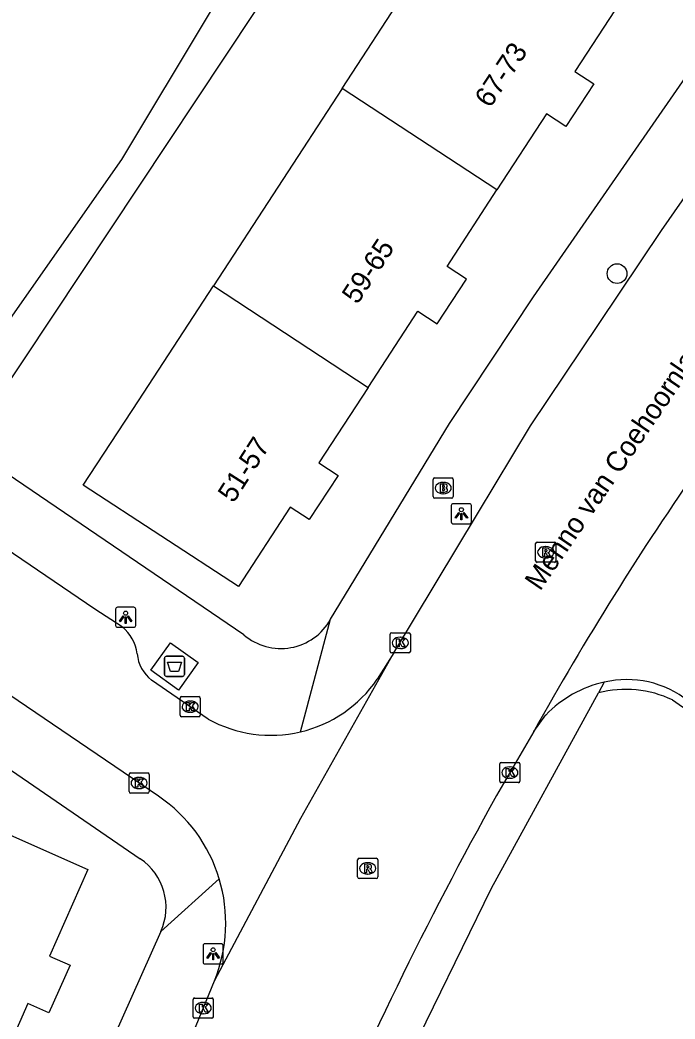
# Model space of a CAD drawing. Extents: x 160026 to 161302, y 384757 to 385701.
# Drawn here: x 160195.38 to 160227.82, y 385434.76 to 385484.27 of the extents above; entities that cross this region are included whole.
import ezdxf

# ---------------------------------------------------------------- set-up
doc = ezdxf.new("R2010")
doc.units = 0
for name, color, linetype in [('IMGEO_Afval_apart_plaats', 7, 'Continuous'), ('IMGEO_Boom', 7, 'Continuous'), ('IMGEO_Brandkraan', 7, 'Continuous'), ('IMGEO_Kolk', 7, 'Continuous'), ('IMGEO_Lichtpunt', 7, 'Continuous'), ('IMGEO_Openbare_ruimte_label', 7, 'Continuous'), ('IMGEO_Pand', 7, 'Continuous'), ('IMGEO_Pand_nummerreeks', 7, 'Continuous'), ('IMGEO_Rijbaan_lokaal_gesloten', 7, 'Continuous'), ('IMGEO_Rijbaan_lokaal_open', 7, 'Continuous'), ('IMGEO_Rioolput', 7, 'Continuous'), ('IMGEO_Voetpad_gesloten', 7, 'Continuous'), ('IMGEO_Voetpad_open', 7, 'Continuous')]:
    doc.layers.add(name, color=color, linetype=linetype)

msp = doc.modelspace()

# ---------------------------------------------------------------- linework, layer by layer
at = {"layer": 'IMGEO_Afval_apart_plaats'}
for p, q in [((160202.534, 385451.837), (160202.534, 385452.637)), ((160202.534, 385452.637), (160202.534, 385451.837)), ((160202.634, 385452.737), (160203.424, 385452.737)), ((160203.424, 385452.737), (160202.634, 385452.737)), ((160203.524, 385452.637), (160203.524, 385451.837)), ((160203.524, 385451.837), (160203.524, 385452.637)), ((160203.424, 385451.737), (160202.634, 385451.737)), ((160202.634, 385451.737), (160203.424, 385451.737))]:
    msp.add_line(p, q, dxfattribs=at)
msp.add_lwpolyline([(160202.677, 385452.451), (160203.381, 385452.451), (160203.232, 385451.981), (160202.826, 385451.981), (160202.677, 385452.451)], dxfattribs=at)
for centre, start, end in [((160202.634, 385452.637), 90, 180), ((160202.634, 385452.637), 90, 180), ((160203.424, 385452.637), 0, 90), ((160203.424, 385452.637), 360, 90), ((160202.634, 385451.837), 180, 270), ((160202.634, 385451.837), 180, 270), ((160203.424, 385451.837), 270, 0), ((160203.424, 385451.837), 270, 0)]:
    msp.add_arc(centre, 0.1, start, end, dxfattribs=at)
at = {"layer": 'IMGEO_Boom'}
msp.add_circle((160224.952, 385471.697), 0.489, dxfattribs=at)
at = {"layer": 'IMGEO_Brandkraan'}
for p, q in [((160215.841, 385460.648), (160215.841, 385461.5)), ((160215.916, 385461.574), (160216.768, 385461.574)), ((160216.842, 385461.5), (160216.842, 385460.648)), ((160216.329, 385461.354), (160216.354, 385461.354)), ((160216.768, 385460.574), (160215.916, 385460.574)), ((160216.352, 385460.794), (160216.327, 385460.794))]:
    msp.add_line(p, q, dxfattribs=at)
for points in [[(160215.841, 385460.648), (160215.841, 385461.5)], [(160215.916, 385461.574), (160216.768, 385461.574)], [(160216.842, 385461.5), (160216.842, 385460.648)], [(160216.189, 385461.274), (160216.189, 385460.874), (160216.402, 385460.874)], [(160216.42, 385461.274), (160216.189, 385461.274)], [(160216.368, 385461.193), (160216.314, 385461.193), (160216.314, 385461.117)], [(160216.314, 385461.117), (160216.367, 385461.117)], [(160216.376, 385461.041), (160216.314, 385461.041), (160216.314, 385460.96)], [(160216.314, 385460.96), (160216.376, 385460.96)], [(160216.768, 385460.574), (160215.916, 385460.574)]]:
    msp.add_lwpolyline(points, dxfattribs=at)
for centre, radius, start, end in [((160215.918, 385461.498), 0.0765, 91.552, 178.448), ((160215.918, 385461.498), 0.0765, 91.552, 178.448), ((160216.766, 385461.498), 0.0765, 1.552, 88.448), ((160216.766, 385461.498), 0.0765, 1.552, 88.448), ((160216.369, 385461.155), 0.0379, 267.8285, 90.9355), ((160216.377, 385461), 0.0404, 269.8759, 90.5077), ((160216.408, 385461.125), 0.251, 268.6676, 293.5347), ((160216.424, 385461.129), 0.145, 59.4692, 91.5367), ((160216.449, 385461.176), 0.0922, 285.5137, 58.1501), ((160216.454, 385460.984), 0.105, 301.3115, 78.989), ((160215.918, 385460.65), 0.0765, 181.552, 268.448), ((160215.918, 385460.65), 0.0765, 181.552, 268.448), ((160216.766, 385460.65), 0.0765, 271.552, 358.448), ((160216.766, 385460.65), 0.0765, 271.552, 358.448)]:
    msp.add_arc(centre, radius, start, end, dxfattribs=at)
for centre, major_axis, ratio, start_param, end_param in [((160216.328, 385461.074), (-0.387, 0.002), 0.722429, 4.712389, 7.853982), ((160216.353, 385461.074), (-0.39, 0.002), 0.717154, 1.570796, 4.712389)]:
    msp.add_ellipse(centre, major_axis=major_axis, ratio=ratio, start_param=start_param, end_param=end_param, dxfattribs=at)
at = {"layer": 'IMGEO_Kolk'}
for p, q in [((160213.714, 385452.975), (160213.714, 385453.827)), ((160213.789, 385453.901), (160214.641, 385453.901)), ((160214.202, 385453.681), (160214.227, 385453.681)), ((160214.715, 385453.827), (160214.715, 385452.975)), ((160214.225, 385453.121), (160214.2, 385453.121)), ((160214.641, 385452.901), (160213.789, 385452.901)), ((160203.307, 385449.815), (160203.307, 385450.667)), ((160203.382, 385450.741), (160204.234, 385450.741)), ((160203.795, 385450.521), (160203.82, 385450.521)), ((160204.308, 385450.667), (160204.308, 385449.815)), ((160204.234, 385449.741), (160203.382, 385449.741)), ((160203.818, 385449.961), (160203.793, 385449.961)), ((160219.142, 385446.549), (160219.142, 385447.401)), ((160219.217, 385447.475), (160220.069, 385447.475)), ((160219.63, 385447.255), (160219.655, 385447.255)), ((160220.143, 385447.401), (160220.143, 385446.549)), ((160200.779, 385446.031), (160200.779, 385446.883)), ((160200.854, 385446.957), (160201.706, 385446.957)), ((160201.267, 385446.737), (160201.292, 385446.737)), ((160201.78, 385446.883), (160201.78, 385446.031)), ((160219.653, 385446.695), (160219.628, 385446.695)), ((160201.29, 385446.177), (160201.265, 385446.177)), ((160220.069, 385446.475), (160219.217, 385446.475)), ((160201.706, 385445.957), (160200.854, 385445.957)), ((160203.954, 385434.878), (160203.954, 385435.73)), ((160204.029, 385435.804), (160204.881, 385435.804)), ((160204.955, 385435.73), (160204.955, 385434.878)), ((160204.442, 385435.584), (160204.467, 385435.584)), ((160204.881, 385434.804), (160204.029, 385434.804)), ((160204.465, 385435.024), (160204.44, 385435.024))]:
    msp.add_line(p, q, dxfattribs=at)
for points in [[(160213.714, 385452.975), (160213.714, 385453.827)], [(160213.789, 385453.901), (160214.641, 385453.901)], [(160214.035, 385453.601), (160214.158, 385453.601), (160214.158, 385453.45), (160214.288, 385453.601), (160214.452, 385453.601), (160214.306, 385453.45), (160214.459, 385453.201), (160214.307, 385453.201), (160214.222, 385453.365), (160214.158, 385453.298), (160214.158, 385453.201), (160214.035, 385453.201), (160214.035, 385453.601)], [(160214.715, 385453.827), (160214.715, 385452.975)], [(160214.641, 385452.901), (160213.789, 385452.901)], [(160203.307, 385449.815), (160203.307, 385450.667)], [(160203.382, 385450.741), (160204.234, 385450.741)], [(160204.308, 385450.667), (160204.308, 385449.815)], [(160203.628, 385450.441), (160203.751, 385450.441), (160203.751, 385450.29), (160203.881, 385450.441), (160204.045, 385450.441), (160203.899, 385450.29), (160204.052, 385450.041), (160203.9, 385450.041), (160203.815, 385450.205), (160203.751, 385450.138), (160203.751, 385450.041), (160203.628, 385450.041), (160203.628, 385450.441)], [(160204.234, 385449.741), (160203.382, 385449.741)], [(160219.142, 385446.549), (160219.142, 385447.401)], [(160219.217, 385447.475), (160220.069, 385447.475)], [(160219.463, 385447.175), (160219.586, 385447.175), (160219.586, 385447.024), (160219.716, 385447.175), (160219.88, 385447.175), (160219.734, 385447.024), (160219.887, 385446.775), (160219.735, 385446.775), (160219.65, 385446.939), (160219.586, 385446.872), (160219.586, 385446.775), (160219.463, 385446.775), (160219.463, 385447.175)], [(160220.143, 385447.401), (160220.143, 385446.549)], [(160200.779, 385446.031), (160200.779, 385446.883)], [(160200.854, 385446.957), (160201.706, 385446.957)], [(160201.1, 385446.657), (160201.223, 385446.657), (160201.223, 385446.506), (160201.353, 385446.657), (160201.517, 385446.657), (160201.371, 385446.506), (160201.524, 385446.257), (160201.372, 385446.257), (160201.287, 385446.421), (160201.223, 385446.354), (160201.223, 385446.257), (160201.1, 385446.257), (160201.1, 385446.657)], [(160201.78, 385446.883), (160201.78, 385446.031)], [(160220.069, 385446.475), (160219.217, 385446.475)], [(160201.706, 385445.957), (160200.854, 385445.957)], [(160203.954, 385434.878), (160203.954, 385435.73)], [(160204.029, 385435.804), (160204.881, 385435.804)], [(160204.955, 385435.73), (160204.955, 385434.878)], [(160204.275, 385435.504), (160204.398, 385435.504), (160204.398, 385435.353), (160204.528, 385435.504), (160204.692, 385435.504), (160204.546, 385435.353), (160204.699, 385435.104), (160204.547, 385435.104), (160204.462, 385435.268), (160204.398, 385435.201), (160204.398, 385435.104), (160204.275, 385435.104), (160204.275, 385435.504)], [(160204.881, 385434.804), (160204.029, 385434.804)]]:
    msp.add_lwpolyline(points, dxfattribs=at)
for centre, start, end in [((160213.791, 385453.825), 91.552, 178.448), ((160213.791, 385453.825), 91.552, 178.448), ((160214.639, 385453.825), 1.552, 88.448), ((160214.639, 385453.825), 1.552, 88.448), ((160213.791, 385452.977), 181.552, 268.448), ((160213.791, 385452.977), 181.552, 268.448), ((160214.639, 385452.977), 271.552, 358.448), ((160214.639, 385452.977), 271.552, 358.448), ((160203.384, 385450.665), 91.552, 178.448), ((160203.384, 385450.665), 91.552, 178.448), ((160204.232, 385450.665), 1.552, 88.448), ((160204.232, 385450.665), 1.552, 88.448), ((160203.384, 385449.817), 181.552, 268.448), ((160203.384, 385449.817), 181.552, 268.448), ((160204.232, 385449.817), 271.552, 358.448), ((160204.232, 385449.817), 271.552, 358.448), ((160219.219, 385447.399), 91.552, 178.448), ((160219.219, 385447.399), 91.552, 178.448), ((160220.067, 385447.399), 1.552, 88.448), ((160220.067, 385447.399), 1.552, 88.448), ((160200.856, 385446.881), 91.552, 178.448), ((160200.856, 385446.881), 91.552, 178.448), ((160201.704, 385446.881), 1.552, 88.448), ((160201.704, 385446.881), 1.552, 88.448), ((160219.219, 385446.551), 181.552, 268.448), ((160219.219, 385446.551), 181.552, 268.448), ((160220.067, 385446.551), 271.552, 358.448), ((160220.067, 385446.551), 271.552, 358.448), ((160200.856, 385446.033), 181.552, 268.448), ((160200.856, 385446.033), 181.552, 268.448), ((160201.704, 385446.033), 271.552, 358.448), ((160201.704, 385446.033), 271.552, 358.448), ((160204.031, 385435.728), 91.552, 178.448), ((160204.031, 385435.728), 91.552, 178.448), ((160204.879, 385435.728), 1.552, 88.448), ((160204.879, 385435.728), 1.552, 88.448), ((160204.031, 385434.88), 181.552, 268.448), ((160204.031, 385434.88), 181.552, 268.448), ((160204.879, 385434.88), 271.552, 358.448), ((160204.879, 385434.88), 271.552, 358.448)]:
    msp.add_arc(centre, 0.0765, start, end, dxfattribs=at)
for centre, major_axis, ratio, start_param, end_param in [((160214.201, 385453.401), (-0.387, 0.002), 0.722429, 4.712389, 7.853982), ((160214.226, 385453.401), (-0.39, 0.002), 0.717154, 1.570796, 4.712389), ((160203.794, 385450.241), (-0.387, 0.002), 0.722429, 4.712389, 7.853982), ((160203.819, 385450.241), (-0.39, 0.002), 0.717154, 1.570796, 4.712389), ((160219.629, 385446.975), (-0.387, 0.002), 0.722429, 4.712389, 7.853982), ((160219.654, 385446.975), (-0.39, 0.002), 0.717154, 1.570796, 4.712389), ((160201.266, 385446.457), (-0.387, 0.002), 0.722429, 4.712389, 7.853982), ((160201.291, 385446.457), (-0.39, 0.002), 0.717154, 1.570796, 4.712389), ((160204.441, 385435.304), (-0.387, 0.002), 0.722429, 4.712389, 7.853982), ((160204.466, 385435.304), (-0.39, 0.002), 0.717154, 1.570796, 4.712389)]:
    msp.add_ellipse(centre, major_axis=major_axis, ratio=ratio, start_param=start_param, end_param=end_param, dxfattribs=at)
at = {"layer": 'IMGEO_Lichtpunt'}
for p, q in [((160216.742, 385460.201), (160216.742, 385459.394)), ((160216.742, 385460.201), (160216.742, 385459.394)), ((160217.644, 385460.296), (160216.836, 385460.296)), ((160217.644, 385460.296), (160216.836, 385460.296)), ((160217.738, 385459.394), (160217.738, 385460.201)), ((160217.738, 385459.394), (160217.738, 385460.201)), ((160216.836, 385459.3), (160217.644, 385459.3)), ((160216.836, 385459.3), (160217.644, 385459.3)), ((160200.113, 385455.075), (160200.113, 385454.268)), ((160200.113, 385455.075), (160200.113, 385454.268)), ((160201.015, 385455.17), (160200.207, 385455.17)), ((160201.015, 385455.17), (160200.207, 385455.17)), ((160201.109, 385454.268), (160201.109, 385455.075)), ((160201.109, 385454.268), (160201.109, 385455.075)), ((160200.207, 385454.174), (160201.015, 385454.174)), ((160200.207, 385454.174), (160201.015, 385454.174)), ((160204.447, 385438.394), (160204.447, 385437.587)), ((160204.447, 385438.394), (160204.447, 385437.587)), ((160205.349, 385438.489), (160204.541, 385438.489)), ((160205.349, 385438.489), (160204.541, 385438.489)), ((160205.443, 385437.587), (160205.443, 385438.394)), ((160205.443, 385437.587), (160205.443, 385438.394)), ((160204.541, 385437.493), (160205.349, 385437.493)), ((160204.541, 385437.493), (160205.349, 385437.493))]:
    msp.add_line(p, q, dxfattribs=at)
for points in [[(160217.116, 385459.865), (160217.155, 385459.837), (160216.967, 385459.575), (160216.929, 385459.602), (160217.116, 385459.865)], [(160217.218, 385459.817), (160217.265, 385459.817), (160217.265, 385459.495), (160217.218, 385459.495), (160217.218, 385459.817)], [(160217.328, 385459.837), (160217.366, 385459.864), (160217.553, 385459.602), (160217.514, 385459.574), (160217.328, 385459.837)], [(160200.487, 385454.739), (160200.526, 385454.711), (160200.338, 385454.449), (160200.3, 385454.476), (160200.487, 385454.739)], [(160200.589, 385454.691), (160200.636, 385454.691), (160200.636, 385454.369), (160200.589, 385454.369), (160200.589, 385454.691)], [(160200.699, 385454.711), (160200.737, 385454.738), (160200.924, 385454.476), (160200.885, 385454.448), (160200.699, 385454.711)], [(160204.821, 385438.058), (160204.86, 385438.03), (160204.672, 385437.768), (160204.634, 385437.795), (160204.821, 385438.058)], [(160204.923, 385438.01), (160204.97, 385438.01), (160204.97, 385437.688), (160204.923, 385437.688), (160204.923, 385438.01)], [(160205.033, 385438.03), (160205.071, 385438.057), (160205.258, 385437.795), (160205.219, 385437.767), (160205.033, 385438.03)]]:
    msp.add_lwpolyline(points, dxfattribs=at)
for centre in [(160217.241, 385459.999), (160200.612, 385454.873), (160204.946, 385438.192)]:
    msp.add_circle(centre, 0.0994, dxfattribs=at)
for centre, start, end in [((160216.836, 385460.201), 90, 180), ((160216.836, 385460.201), 90, 180), ((160217.644, 385460.201), 0, 90), ((160217.644, 385460.201), 0, 90), ((160216.836, 385459.394), 180, 270), ((160216.836, 385459.394), 180, 270), ((160217.644, 385459.394), 270, 0), ((160217.644, 385459.394), 270, 360), ((160200.207, 385455.075), 90, 180), ((160200.207, 385455.075), 90, 180), ((160201.015, 385455.075), 0, 90), ((160201.015, 385455.075), 0, 90), ((160200.207, 385454.268), 180, 270), ((160200.207, 385454.268), 180, 270), ((160201.015, 385454.268), 270, 0), ((160201.015, 385454.268), 270, 360), ((160204.541, 385438.394), 90, 180), ((160204.541, 385438.394), 90, 180), ((160205.349, 385438.394), 0, 90), ((160205.349, 385438.394), 0, 90), ((160204.541, 385437.587), 180, 270), ((160204.541, 385437.587), 180, 270), ((160205.349, 385437.587), 270, 0), ((160205.349, 385437.587), 270, 360)]:
    msp.add_arc(centre, 0.0946, start, end, dxfattribs=at)
at = {"layer": 'IMGEO_Pand'}
for points in [[(160211.338, 385480.879), (160217.716, 385490.66), (160221.229, 385488.37), (160225.417, 385485.639), (160222.862, 385481.721), (160223.802, 385481.107), (160222.422, 385478.99), (160221.46, 385479.617), (160219.002, 385475.848)], [(160211.338, 385480.879), (160204.96, 385471.099)], [(160219.002, 385475.848), (160211.338, 385480.879)], [(160212.629, 385466.064), (160215.087, 385469.833), (160216.041, 385469.211), (160217.489, 385471.432), (160216.53, 385472.058), (160219.002, 385475.848)], [(160212.629, 385466.064), (160210.185, 385462.317), (160211.131, 385461.7), (160209.706, 385459.515), (160208.766, 385460.128), (160206.202, 385456.196), (160198.512, 385461.212), (160201.244, 385465.401), (160204.96, 385471.099)], [(160204.96, 385471.099), (160212.629, 385466.064)], [(160185.543, 385435.246), (160190.285, 385445.923), (160198.736, 385442.169), (160196.832, 385437.882), (160197.864, 385437.424), (160196.815, 385435.064), (160195.773, 385435.527), (160193.983, 385431.497)]]:
    msp.add_lwpolyline(points, dxfattribs=at)
at = {"layer": 'IMGEO_Rijbaan_lokaal_gesloten'}
for points in [[(160213.889, 385452.911), (160218.042, 385459.796), (160220.662, 385464.164), (160224.069, 385469.234), (160227.148, 385473.834), (160229.85, 385477.702), (160233.05, 385482.043), (160237.154, 385487.587), (160240.762, 385492.238), (160247.036, 385500), (160248.366, 385501.543), (160249.437, 385502.831)], [(160205.006, 385436.649), (160209.284, 385444.718), (160213.889, 385452.911)], [(160220.83, 385449.016), (160218.975, 385445.832)], [(160202.176, 385429.732), (160205.006, 385436.649)]]:
    msp.add_lwpolyline(points, dxfattribs=at)
for centre, radius, start, end in [((160357.629, 385372.773), 156.611, 145.14571, 150.86761), ((160401.739, 385344.741), 208.859, 151.05207, 156.9001)]:
    msp.add_arc(centre, radius, start, end, dxfattribs=at)
at = {"layer": 'IMGEO_Rijbaan_lokaal_open'}
for points in [[(160200.435, 385454.194), (160199.088, 385455.07), (160180.167, 385467.938), (160175.915, 385470.845)], [(160202.245, 385445.802), (160185.235, 385457.355)], [(160213.889, 385452.911), (160213.073, 385451.597)], [(160204.698, 385449.628), (160201.897, 385451.558)], [(160220.83, 385449.016), (160221.42, 385449.828)]]:
    msp.add_lwpolyline(points, dxfattribs=at)
for centre, radius, start, end in [((160199.215, 385452.641), 1.975, 6.3384, 51.8582), ((160203.067, 385453.054), 1.899, 185.8816, 231.973), ((160207.805, 385455.206), 6.385, 283.2337, 325.5863), ((160225.436, 385446.716), 4.869, 51.2626, 103.2253), ((160225.581, 385445.811), 5.783, 102.5731, 136.0111), ((160207.806, 385455.207), 6.386, 240.8774, 283.2242), ((160197.984, 385439.524), 7.587, 16.7816, 55.833), ((160197.987, 385439.523), 7.584, 337.7317, 16.7985)]:
    msp.add_arc(centre, radius, start, end, dxfattribs=at)
at = {"layer": 'IMGEO_Rioolput'}
for p, q in [((160220.919, 385457.467), (160220.919, 385458.319)), ((160220.994, 385458.393), (160221.846, 385458.393)), ((160221.407, 385458.173), (160221.432, 385458.173)), ((160221.92, 385458.319), (160221.92, 385457.467)), ((160221.43, 385457.613), (160221.405, 385457.613)), ((160221.846, 385457.393), (160220.994, 385457.393)), ((160212.101, 385441.802), (160212.101, 385442.654)), ((160212.176, 385442.728), (160213.028, 385442.728)), ((160213.102, 385442.654), (160213.102, 385441.802)), ((160212.589, 385442.508), (160212.614, 385442.508)), ((160213.028, 385441.728), (160212.176, 385441.728)), ((160212.612, 385441.948), (160212.587, 385441.948))]:
    msp.add_line(p, q, dxfattribs=at)
for points in [[(160220.919, 385457.467), (160220.919, 385458.319)], [(160220.994, 385458.393), (160221.846, 385458.393)], [(160221.508, 385458.091), (160221.256, 385458.093), (160221.256, 385457.693)], [(160221.434, 385458.012), (160221.38, 385458.012), (160221.38, 385457.931)], [(160221.38, 385457.931), (160221.432, 385457.931)], [(160221.92, 385458.319), (160221.92, 385457.467)], [(160221.256, 385457.693), (160221.38, 385457.693), (160221.38, 385457.855), (160221.391, 385457.855)], [(160221.438, 385457.826), (160221.509, 385457.693), (160221.649, 385457.693), (160221.584, 385457.819)], [(160221.846, 385457.393), (160220.994, 385457.393)], [(160212.101, 385441.802), (160212.101, 385442.654)], [(160212.176, 385442.728), (160213.028, 385442.728)], [(160213.102, 385442.654), (160213.102, 385441.802)], [(160212.69, 385442.426), (160212.438, 385442.428), (160212.438, 385442.028)], [(160212.438, 385442.028), (160212.562, 385442.028), (160212.562, 385442.19), (160212.573, 385442.19)], [(160212.616, 385442.347), (160212.562, 385442.347), (160212.562, 385442.266)], [(160212.562, 385442.266), (160212.614, 385442.266)], [(160212.62, 385442.161), (160212.691, 385442.028), (160212.831, 385442.028), (160212.766, 385442.154)], [(160213.028, 385441.728), (160212.176, 385441.728)]]:
    msp.add_lwpolyline(points, dxfattribs=at)
for centre, radius, start, end in [((160220.996, 385458.317), 0.0765, 91.552, 178.448), ((160220.996, 385458.317), 0.0765, 91.552, 178.448), ((160221.416, 385458.12), 0.19, 274.7715, 282.9687), ((160221.44, 385457.916), 0.0964, 77.0061, 93.1865), ((160221.454, 385457.973), 0.0378, 276.6634, 79.6772), ((160221.507, 385457.981), 0.109, 350.3612, 89.416), ((160221.505, 385457.981), 0.112, 277.5842, 350.9817), ((160221.844, 385458.317), 0.0765, 1.552, 88.448), ((160221.844, 385458.317), 0.0765, 1.552, 88.448), ((160220.996, 385457.469), 0.0765, 181.552, 268.448), ((160220.996, 385457.469), 0.0765, 181.552, 268.448), ((160221.39, 385457.802), 0.0533, 26.0293, 88.6989), ((160221.489, 385457.766), 0.108, 29.5134, 73.7905), ((160221.844, 385457.469), 0.0765, 271.552, 358.448), ((160221.844, 385457.469), 0.0765, 271.552, 358.448), ((160212.178, 385442.652), 0.0765, 91.552, 178.448), ((160212.178, 385442.652), 0.0765, 91.552, 178.448), ((160213.026, 385442.652), 0.0765, 1.552, 88.448), ((160213.026, 385442.652), 0.0765, 1.552, 88.448), ((160212.572, 385442.137), 0.0533, 26.0293, 88.6989), ((160212.598, 385442.455), 0.19, 274.7715, 282.9687), ((160212.622, 385442.251), 0.0964, 77.0061, 93.1865), ((160212.636, 385442.308), 0.0378, 276.6634, 79.6772), ((160212.689, 385442.316), 0.109, 350.3612, 89.416), ((160212.687, 385442.316), 0.112, 277.5842, 350.9817), ((160212.671, 385442.101), 0.108, 29.5134, 73.7905), ((160212.178, 385441.804), 0.0765, 181.552, 268.448), ((160212.178, 385441.804), 0.0765, 181.552, 268.448), ((160213.026, 385441.804), 0.0765, 271.552, 358.448), ((160213.026, 385441.804), 0.0765, 271.552, 358.448)]:
    msp.add_arc(centre, radius, start, end, dxfattribs=at)
for centre, major_axis, ratio, start_param, end_param in [((160221.406, 385457.893), (-0.387, 0.002), 0.722429, 4.712389, 7.853982), ((160221.431, 385457.893), (-0.39, 0.002), 0.717154, 1.570796, 4.712389), ((160212.588, 385442.228), (-0.387, 0.002), 0.722429, 4.712389, 7.853982), ((160212.613, 385442.228), (-0.39, 0.002), 0.717154, 1.570796, 4.712389)]:
    msp.add_ellipse(centre, major_axis=major_axis, ratio=ratio, start_param=start_param, end_param=end_param, dxfattribs=at)
at = {"layer": 'IMGEO_Voetpad_gesloten'}
msp.add_lwpolyline([(160202.826, 385453.408), (160204.203, 385452.427), (160203.233, 385451.065), (160201.856, 385452.046), (160202.826, 385453.408)], dxfattribs=at)
at = {"layer": 'IMGEO_Voetpad_open'}
for points in [[(160191.188, 385464.185), (160200.423, 385477.359), (160213.246, 385498.748), (160215.8, 385502.686), (160216.228, 385502.359), (160218.318, 385504.995), (160218.845, 385504.672), (160233.689, 385522.91)], [(160192.707, 385463.153), (160214.103, 385495.368), (160230.744, 385484.695)], [(160210.759, 385454.57), (160216.645, 385464.267), (160220.806, 385470.55), (160229.051, 385482.447), (160230.744, 385484.695)], [(160206.465, 385453.803), (160192.707, 385463.153)], [(160209.267, 385448.99), (160210.759, 385454.57)], [(160187.987, 385451.859), (160201.338, 385442.708)], [(160224.322, 385451.456), (160224.032, 385450.925)], [(160209.287, 385420.485), (160210.991, 385424.828), (160212.991, 385429.483), (160218.738, 385441.239), (160224.032, 385450.925)], [(160227.7, 385450.572), (160231.739, 385447.754)], [(160202.358, 385439.094), (160205.248, 385441.715)], [(160202.358, 385439.094), (160183.335, 385396.478)]]:
    msp.add_lwpolyline(points, dxfattribs=at)
for centre, radius, start, end in [((160208.3, 385455.932), 2.811, 229.2426, 331.0123), ((160225.379, 385445.689), 5.407, 64.5788, 104.4271), ((160199.679, 385440.289), 2.933, 335.9618, 55.5601)]:
    msp.add_arc(centre, radius, start, end, dxfattribs=at)

# ---------------------------------------------------------------- texts
at = {"layer": 'IMGEO_Openbare_ruimte_label'}
msp.add_text('Menno van Coehoornlaan', height=1, rotation=55.7217, dxfattribs=at).set_placement((160221.14, 385455.935))
at = {"layer": 'IMGEO_Pand_nummerreeks'}
for s, rotation, p in [('67-73', 56.411, (160218.665, 385479.863)), ('59-65', 56.7683, (160212.091, 385470.128)), ('51-57', 57.4302, (160205.955, 385460.286))]:
    msp.add_text(s, height=1, rotation=rotation, dxfattribs=at).set_placement(p)

doc.saveas('drawing.dxf')
